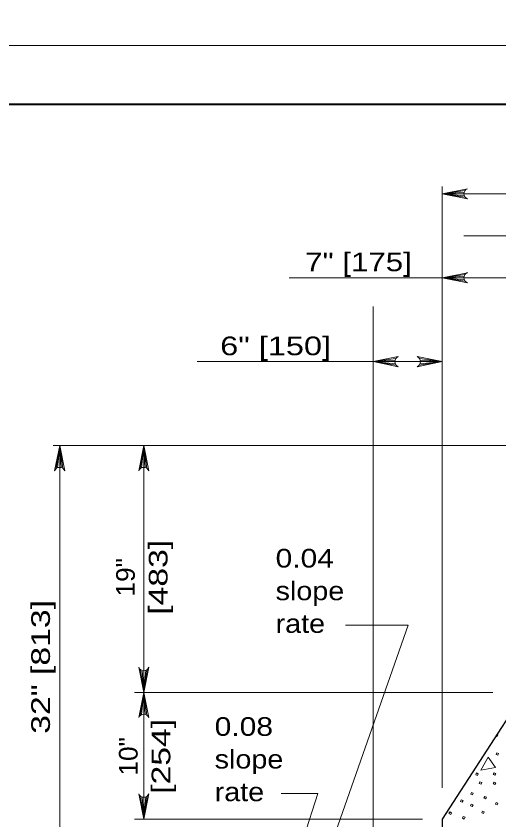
# Model space of a CAD drawing. Extents: x -1431.2 to -1397.2, y -1045.1 to -1001.1.
# Drawn here: x -1426.39 to -1422.28, y -1029.67 to -1022.83 of the extents above; entities that cross this region are included whole.
import ezdxf
from ezdxf.enums import TextEntityAlignment as Align

# ---------------------------------------------------------------- set-up
doc = ezdxf.new("R2010")
doc.units = 0
doc.header["$LTSCALE"] = 0.064
doc.linetypes.add('LONG_DASHED', pattern=[7.5, 6, -1.5])
doc.layers.add('1', color=7, linetype='Continuous', lineweight=13)

msp = doc.modelspace()

# ---------------------------------------------------------------- linework, layer by layer
at = {"layer": '1', "lineweight": 25}
msp.add_line((-1429.24575, -1023.57983), (-1397.74575, -1023.57983), dxfattribs=at)
at = {"layer": '1'}
for p, q in [((-1422.764, -1029.39758), (-1422.764, -1024.27858)), ((-1422.57033, -1024.31433), (-1422.764, -1024.34142)), ((-1422.57692, -1024.32775), (-1422.764, -1024.34142)), ((-1422.57892, -1024.34142), (-1422.764, -1024.34142)), ((-1422.5755, -1024.35883), (-1422.764, -1024.34142)), ((-1422.56808, -1024.37133), (-1422.764, -1024.34142)), ((-1420.594, -1024.34142), (-1422.764, -1024.34142)), ((-1422.06608, -1024.69867), (-1422.58025, -1024.69867)), ((-1422.06608, -1025.05583), (-1424.0665, -1025.05583)), ((-1422.57033, -1025.02875), (-1422.764, -1025.05583)), ((-1422.57692, -1025.04217), (-1422.764, -1025.05583)), ((-1422.57892, -1025.05583), (-1422.764, -1025.05583)), ((-1422.5755, -1025.07325), (-1422.764, -1025.05583)), ((-1422.56808, -1025.08583), (-1422.764, -1025.05583)), ((-1423.35233, -1029.98658), (-1423.35233, -1025.30175)), ((-1423.15867, -1025.74317), (-1423.35233, -1025.77033)), ((-1423.16517, -1025.75658), (-1423.35233, -1025.77033)), ((-1423.16717, -1025.77033), (-1423.35233, -1025.77033)), ((-1423.16375, -1025.78767), (-1423.35233, -1025.77033)), ((-1423.15633, -1025.80025), (-1423.35233, -1025.77033)), ((-1422.96, -1025.80025), (-1422.764, -1025.77033)), ((-1422.95258, -1025.78767), (-1422.764, -1025.77033)), ((-1422.95117, -1025.75658), (-1422.764, -1025.77033)), ((-1422.94917, -1025.77033), (-1422.764, -1025.77033)), ((-1422.764, -1026.48475), (-1426.072, -1026.48475)), ((-1426.04617, -1026.68067), (-1426.01625, -1026.48467)), ((-1426.03367, -1026.67325), (-1426.01625, -1026.48467)), ((-1426.01625, -1029.98658), (-1426.01625, -1026.48467)), ((-1426.01625, -1026.66983), (-1426.01625, -1026.48467)), ((-1426.00258, -1026.67183), (-1426.01625, -1026.48467)), ((-1425.98917, -1026.67842), (-1426.01625, -1026.48467)), ((-1425.33175, -1026.68067), (-1425.30183, -1026.48467)), ((-1425.31917, -1026.67325), (-1425.30183, -1026.48467)), ((-1425.30183, -1026.66983), (-1425.30183, -1026.48467)), ((-1425.28808, -1026.67183), (-1425.30183, -1026.48467)), ((-1425.27467, -1026.67842), (-1425.30183, -1026.48467)), ((-1425.30183, -1028.55317), (-1425.30183, -1026.48467)), ((-1421.87667, -1026.48467), (-1422.99725, -1026.48467)), ((-1423.73725, -1029.96667), (-1423.05292, -1028.01158)), ((-1423.58533, -1028.01158), (-1423.05292, -1028.01158)), ((-1425.32892, -1028.39117), (-1425.30183, -1028.58492)), ((-1425.3155, -1028.39775), (-1425.30183, -1028.58492)), ((-1425.27183, -1028.38892), (-1425.30183, -1028.58492)), ((-1425.28442, -1028.39633), (-1425.30183, -1028.58492)), ((-1425.30183, -1028.39975), (-1425.30183, -1028.58492)), ((-1422.3325, -1028.58492), (-1425.38117, -1028.58492)), ((-1425.33175, -1028.78083), (-1425.30183, -1028.58492)), ((-1425.31917, -1028.77342), (-1425.30183, -1028.58492)), ((-1425.30183, -1028.77), (-1425.30183, -1028.58492)), ((-1425.28808, -1028.772), (-1425.30183, -1028.58492)), ((-1425.27467, -1028.77858), (-1425.30183, -1028.58492)), ((-1425.30183, -1029.662), (-1425.30183, -1028.58492)), ((-1425.32892, -1029.46833), (-1425.30183, -1029.662)), ((-1425.3155, -1029.47492), (-1425.30183, -1029.662)), ((-1425.27183, -1029.466), (-1425.30183, -1029.662)), ((-1425.28442, -1029.47342), (-1425.30183, -1029.662)), ((-1425.30183, -1029.47692), (-1425.30183, -1029.662)), ((-1424.13317, -1029.44358), (-1423.82075, -1029.44358)), ((-1424.05033, -1030.15275), (-1423.82075, -1029.44358)), ((-1422.93275, -1029.662), (-1425.38117, -1029.662))]:
    msp.add_line(p, q, dxfattribs=at)
at = {"layer": '1', "linetype": 'LONG_DASHED'}
for points in [[(-1431.24575, -1023.07983), (-1397.24575, -1023.07983), (-1397.24575, -1001.07983), (-1431.24575, -1001.07983)], [(-1431.24575, -1045.07983), (-1397.24575, -1045.07983), (-1397.24575, -1023.07983), (-1431.24575, -1023.07983)]]:
    msp.add_lwpolyline(points, close=True, dxfattribs=at)
at = {"layer": '1', "lineweight": 40}
msp.add_lwpolyline([(-1429.24575, -1023.57983), (-1397.74575, -1023.57983), (-1397.74575, -1044.57983), (-1429.24575, -1044.57983)], close=True, dxfattribs=at)
at = {"layer": '1'}
for points in [[(-1422.55008, -1024.38417), (-1422.764, -1024.34142), (-1422.55008, -1024.29858)], [(-1422.55008, -1025.09867), (-1422.764, -1025.05583), (-1422.55008, -1025.01308)], [(-1422.95775, -1025.74317), (-1422.764, -1025.77033), (-1424.84775, -1025.77033)], [(-1423.13842, -1025.81308), (-1423.35233, -1025.77033), (-1423.13842, -1025.7275)], [(-1422.978, -1025.81308), (-1422.764, -1025.77033), (-1422.978, -1025.7275)], [(-1426.059, -1026.69867), (-1426.01625, -1026.48467), (-1425.97342, -1026.69867)], [(-1425.34458, -1026.69867), (-1425.30183, -1026.48467), (-1425.259, -1026.69867)], [(-1425.259, -1028.37092), (-1425.30183, -1028.58492), (-1425.34458, -1028.37092)], [(-1425.34458, -1028.79883), (-1425.30183, -1028.58492), (-1425.259, -1028.79883)], [(-1422.29742, -1028.94192), (-1422.29117, -1028.94442), (-1422.29725, -1028.9585), (-1422.30592, -1028.95508)], [(-1425.259, -1029.44808), (-1425.30183, -1029.662), (-1425.34458, -1029.44808)]]:
    msp.add_lwpolyline(points, dxfattribs=at)
at = {"layer": '1', "lineweight": 25}
msp.add_lwpolyline([(-1421.842, -1026.66275), (-1422.06608, -1028.58492), (-1422.764, -1029.662), (-1422.764, -1030.21375), (-1423.35233, -1030.21375)], dxfattribs=at)
at = {"layer": '1'}
for points in [[(-1422.37375, -1029.13467), (-1422.43617, -1029.24642), (-1422.31233, -1029.22225)], [(-1422.29925, -1029.09742), (-1422.28417, -1029.1035), (-1422.29017, -1029.11758), (-1422.30533, -1029.1115)], [(-1422.47342, -1029.26958), (-1422.45833, -1029.27667), (-1422.46442, -1029.29075), (-1422.4795, -1029.28467)], [(-1422.32342, -1029.26958), (-1422.30833, -1029.27567), (-1422.31533, -1029.28975), (-1422.3305, -1029.28367)], [(-1422.44325, -1029.34508), (-1422.42817, -1029.35217), (-1422.43417, -1029.36625), (-1422.44925, -1029.35917)], [(-1422.32342, -1029.34808), (-1422.30833, -1029.35417), (-1422.31533, -1029.36925), (-1422.3305, -1029.36225)], [(-1422.51575, -1029.43567), (-1422.50067, -1029.44275), (-1422.50667, -1029.45683), (-1422.52175, -1029.45083)], [(-1422.60233, -1029.49808), (-1422.58725, -1029.50417), (-1422.59325, -1029.51925), (-1422.60833, -1029.51225)], [(-1422.403, -1029.46992), (-1422.38783, -1029.476), (-1422.39492, -1029.49108), (-1422.41, -1029.484)], [(-1422.51675, -1029.53433), (-1422.50167, -1029.54142), (-1422.50867, -1029.5555), (-1422.52383, -1029.5495)], [(-1422.30633, -1029.52225), (-1422.29117, -1029.52833), (-1422.29725, -1029.54242), (-1422.31233, -1029.53642)], [(-1422.7, -1029.60183), (-1422.68492, -1029.60783), (-1422.69192, -1029.622), (-1422.70708, -1029.61592)], [(-1422.58525, -1029.64108), (-1422.57008, -1029.64708), (-1422.57617, -1029.66225), (-1422.59125, -1029.65517)], [(-1422.42208, -1029.59575), (-1422.407, -1029.60183), (-1422.413, -1029.61592), (-1422.42817, -1029.60983)]]:
    msp.add_lwpolyline(points, close=True, dxfattribs=at)
for centre, start, end in [((-1422.53279, -1024.34135), 112.08782, 247.91395), ((-1422.53279, -1025.0558), 112.08782, 247.91395), ((-1423.12111, -1025.77025), 112.08782, 247.91395), ((-1422.99527, -1025.77025), 292.08605, 67.91218), ((-1426.0162, -1026.71592), 22.08782, 157.91395), ((-1425.30175, -1026.71592), 22.08782, 157.91395), ((-1425.30185, -1028.35365), 202.08782, 337.91395), ((-1425.30175, -1028.81613), 22.08782, 157.91395), ((-1425.30185, -1029.43079), 202.08782, 337.91395)]:
    msp.add_arc(centre, 0.04618, start, end, dxfattribs=at)

# ---------------------------------------------------------------- texts
for s, width, p in [('7" [175]', 1.25, (-1423.47563, -1025.00067)), ('6" [150]', 1.3, (-1424.18058, -1025.71558))]:
    msp.add_text(s, height=0.1588, dxfattribs=dict(at, width=width)).set_placement(p, align=Align.CENTER)
for s, width, p in [('[483]', 1.35, (-1425.0995, -1027.605)), ('19"', 1.05, (-1425.37733, -1027.605)), ('[254]', 1.35, (-1425.07567, -1029.12867)), ('10"', 1.05, (-1425.3535, -1029.12858))]:
    msp.add_text(s, height=0.1588, rotation=90, dxfattribs=dict(at, width=width)).set_placement(p, align=Align.CENTER)
for s, width, p in [('0.04', 1.2, (-1424.18058, -1027.52217)), ('slope', 1.15, (-1424.18058, -1027.8)), ('rate', 1.15, (-1424.18058, -1028.07792)), ('0.08', 1.2, (-1424.6985, -1028.95417)), ('slope', 1.15, (-1424.6985, -1029.232)), ('rate', 1.15, (-1424.6985, -1029.50992))]:
    msp.add_text(s, height=0.1588, dxfattribs=dict(at, width=width)).set_placement(p)
at = {"layer": '1', "width": 1.35}
msp.add_text('32" [813]', height=0.1588, rotation=90, dxfattribs=at).set_placement((-1426.099, -1028.9365))

doc.saveas('drawing.dxf')
